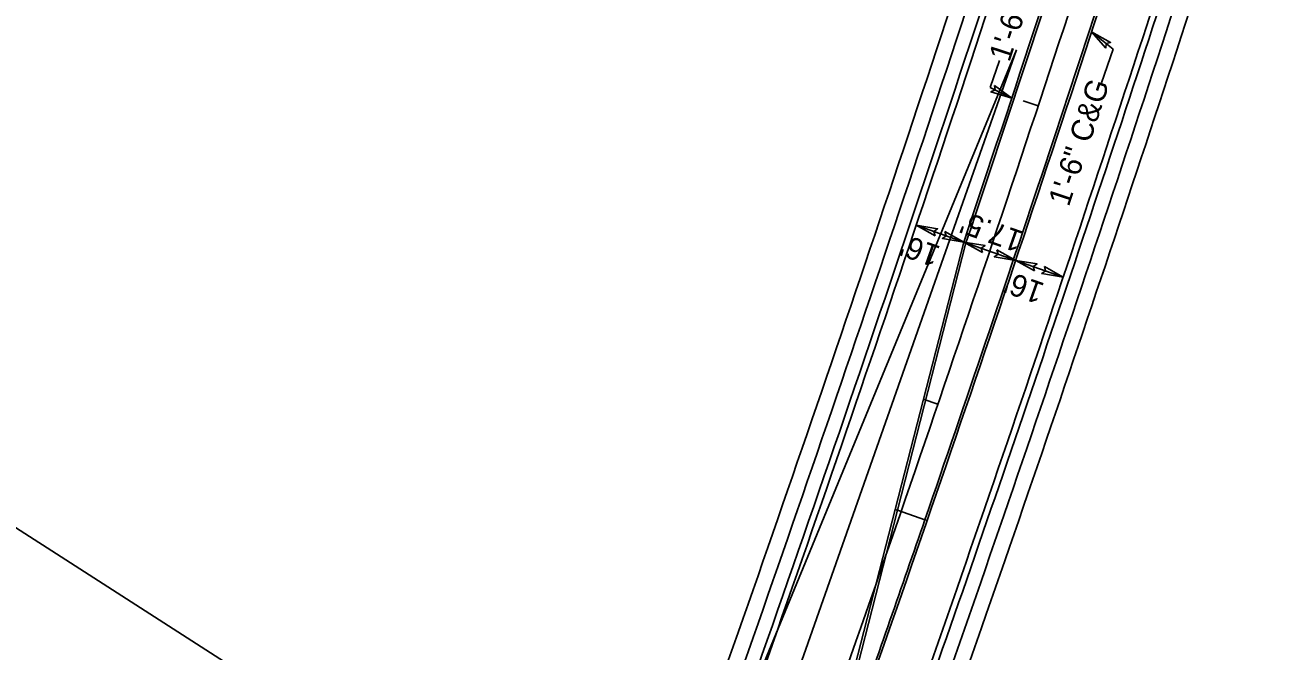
# Model space of a CAD drawing. Extents: x 1974386 to 1979988, y 776712 to 784860.
# Drawn here: x 1977201.1 to 1977597.8, y 781095.4 to 781294.3 of the extents above; entities that cross this region are included whole.
import ezdxf

# ---------------------------------------------------------------- set-up
doc = ezdxf.new("R2010")
doc.units = 0
for name, color, linetype in [('Prop Conc 1ft 6in Curb and Gutter', 7, 'Continuous'), ('Prop Conc 2ft 6in Curb and Gutter', 7, 'Continuous'), ('Prop Conc 4in Sidewalk', 7, 'Continuous'), ('Prop Conc 5in Monolithic Keyed In Island', 7, 'Continuous'), ('Prop Dimension', 7, 'Continuous'), ('Prop Dimension Text', 7, 'Continuous'), ('Prop EOT', 7, 'Continuous'), ('Prop Horizontal Alignment', 7, 'Continuous'), ('Prop Horizontal Alignment Tick Small', 7, 'Continuous'), ('Prop Terminator CELL', 7, 'Continuous'), ('Scratch_Level_1', 7, 'Continuous'), ('Sheet Layout Plan Border', 7, 'Continuous')]:
    doc.layers.add(name, color=color, linetype=linetype)

msp = doc.modelspace()

# ---------------------------------------------------------------- linework, layer by layer
at = {"layer": 'Prop Conc 1ft 6in Curb and Gutter'}
for p, q in [((1977499.95, 781225.07), (1977478.18, 781140.13)), ((1977477.47, 781140.38), (1977478.18, 781140.13)), ((1977487.36, 781136.97), (1977486.92, 781137.12))]:
    msp.add_line(p, q, dxfattribs=at)
for radius, start in [(10992, 341.434732), (11008, 340.97892)]:
    msp.add_arc((1967079.97, 784724.8), radius, start, 342.220851, dxfattribs=at)
at = {"layer": 'Prop Conc 2ft 6in Curb and Gutter'}
for radius, start, end in [(10973.25, 340.626468, 342.297), (11026.75, 340.72417, 342.033223)]:
    msp.add_arc((1967079.97, 784724.8), radius, start, end, dxfattribs=at)
at = {"layer": 'Prop Conc 4in Sidewalk'}
for radius, start in [(10963.75, 340.626468), (10968.75, 340.626468), (11031.25, 340.72417), (11036.25, 340.72417)]:
    msp.add_arc((1967079.97, 784724.8), radius, start, 342.220851, dxfattribs=at)
at = {"layer": 'Prop Conc 5in Monolithic Keyed In Island'}
for p, q in [((1977462.63, 781079.46), (1977478.18, 781140.13)), ((1977478.18, 781140.13), (1977486.92, 781137.12))]:
    msp.add_line(p, q, dxfattribs=at)
msp.add_arc((1967079.97, 784724.8), 11008, 340.626468, 340.97892, dxfattribs=at)
at = {"layer": 'Prop Dimension'}
for p, q in [((1977546.73, 781286.6), (1977539.86, 781292.11)), ((1977542.98, 781275.89), (1977546.73, 781286.6)), ((1977510.6, 781283.06), (1977507.68, 781274.5)), ((1977507.68, 781274.5), (1977514.49, 781271.04)), ((1977484.17, 781230.69), (1977499.26, 781225.36)), ((1977515.76, 781219.53), (1977499.26, 781225.36)), ((1977530.85, 781214.2), (1977515.76, 781219.53))]:
    msp.add_line(p, q, dxfattribs=at)
at = {"layer": 'Prop EOT'}
msp.add_line((1977499.26, 781225.36), (1977461.91, 781079.68), dxfattribs=at)
for radius, start in [(10975.25, 340.626468), (10991.25, 341.434732), (11008.75, 340.626468), (11024.75, 340.72417)]:
    msp.add_arc((1967079.97, 784724.8), radius, start, 342.220851, dxfattribs=at)
at = {"layer": 'Prop Horizontal Alignment'}
msp.add_arc((1967079.97, 784724.8), 11000, 340.626468, 342.220851, dxfattribs=at)
at = {"layer": 'Prop Horizontal Alignment Tick Small'}
for p, q in [((1977522.92, 781268.66), (1977518.17, 781270.23)), ((1977491.07, 781173.87), (1977486.33, 781175.48))]:
    msp.add_line(p, q, dxfattribs=at)
at = {"layer": 'Prop Terminator CELL'}
for points in [[(1977544.4, 781286.98), (1977539.86, 781292.11), (1977545.9, 781288.8), (1977544.48, 781288.4)], [(1977509, 781275.13), (1977514.49, 781271.04), (1977507.89, 781273.04), (1977509.21, 781273.72)], [(1977490.15, 781227.34), (1977484.17, 781230.69), (1977490.97, 781229.56), (1977489.76, 781228.71)], [(1977493.28, 781228.7), (1977499.26, 781225.36), (1977492.46, 781226.49), (1977493.67, 781227.33)], [(1977505.23, 781222.01), (1977499.26, 781225.36), (1977506.06, 781224.23), (1977504.84, 781223.38)], [(1977509.78, 781222.87), (1977515.76, 781219.53), (1977508.96, 781220.66), (1977510.17, 781221.5)], [(1977521.74, 781216.19), (1977515.76, 781219.53), (1977522.56, 781218.4), (1977521.35, 781217.56)], [(1977524.87, 781217.54), (1977530.85, 781214.2), (1977524.05, 781215.33), (1977525.26, 781216.17)]]:
    msp.add_lwpolyline(points, close=True, dxfattribs=at)
at = {"layer": 'Scratch_Level_1'}
for p, q in [((1977516.04, 781286.37), (1977329.74, 780834.25)), ((1977356.9, 780833.79), (1977516.04, 781286.37))]:
    msp.add_line(p, q, dxfattribs=at)
at = {"layer": 'Sheet Layout Plan Border'}
msp.add_lwpolyline([(1977111.11, 779526.05), (1977868.38, 780703.57), (1976985.24, 781271.52), (1976227.97, 780094)], close=True, dxfattribs=at)

# ---------------------------------------------------------------- texts
at = {"layer": 'Prop Dimension'}
for rotation, p in [(71.9343, (1977513.75, 781282.27)), (71.7516, (1977532.6, 781236.33))]:
    msp.add_text('1\'-6" C&G', height=7, rotation=rotation, dxfattribs=at).set_placement(p)
at = {"layer": 'Prop Dimension Text'}
for s, p in [("17.5'", (1977518.64, 781228.48)), ("16'", (1977492.24, 781223.82)), ("16'", (1977525.29, 781212.07))]:
    msp.add_text(s, height=7, rotation=160.5508, dxfattribs=at).set_placement(p)

doc.saveas('drawing.dxf')
